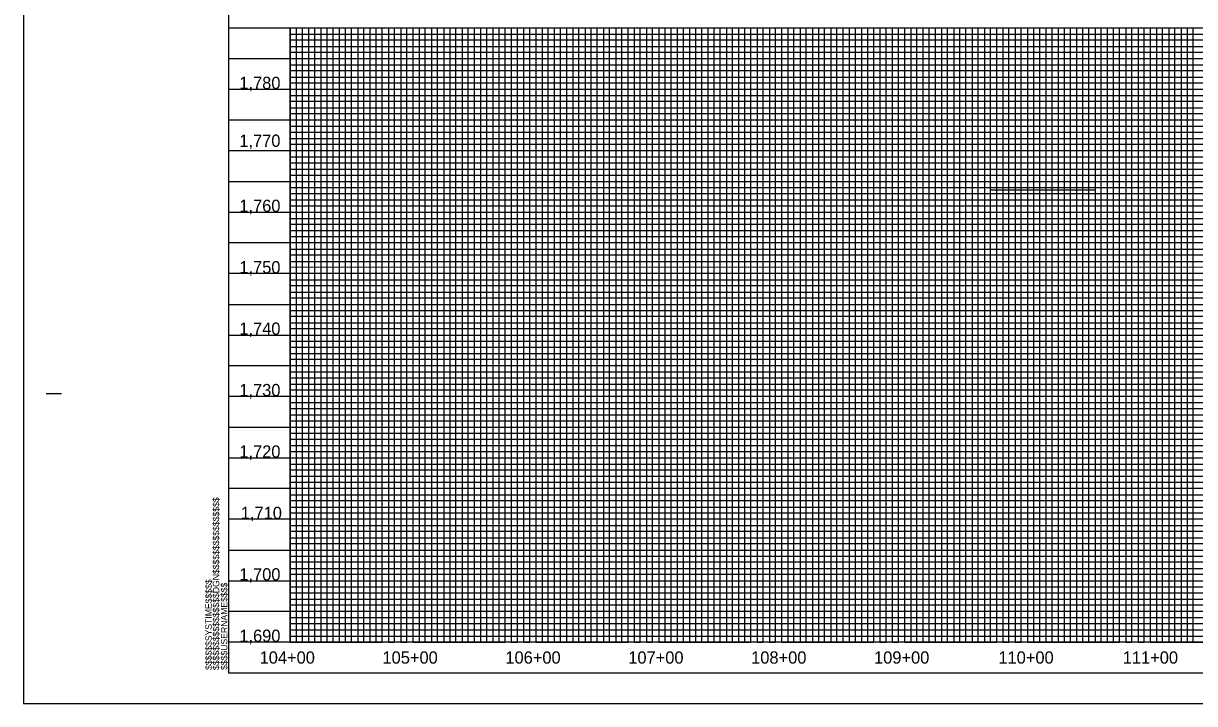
# Model space of a CAD drawing. Extents: x 505602 to 507286, y 483109 to 484209.
# Drawn here: x 505602 to 506555, y 483109 to 483662 of the extents above; entities that cross this region are included whole.
import ezdxf

# ---------------------------------------------------------------- set-up
doc = ezdxf.new("R2010")
doc.units = 0
for name, color, linetype in [('Exist Vertical Profile Vertical Axis Label', 7, 'Continuous'), ('Prop Grid Mask', 7, 'Continuous'), ('Sheet Layout Profile Border Port 2', 7, 'Continuous'), ('Sheet Plot Border Outside CELL', 7, 'Continuous'), ('Sheet Profile CELL', 7, 'Continuous'), ('Sheet Profile Grid Major CELL', 7, 'Continuous'), ('Sheet Profile Grid Middle CELL', 7, 'Continuous'), ('Sheet Profile Grid Minor CELL', 7, 'Continuous')]:
    doc.layers.add(name, color=color, linetype=linetype)

msp = doc.modelspace()

# ---------------------------------------------------------------- linework, layer by layer
at = {"layer": 'Prop Grid Mask'}
msp.add_lwpolyline([(506389.06, 483573.91), (506474.08, 483573.91), (506474.08, 483526.68), (506389.06, 483526.68)], close=True, dxfattribs=at)
at = {"layer": 'Sheet Layout Profile Border Port 2'}
msp.add_lwpolyline([(505819.08, 483658.71), (507219.08, 483658.71), (507219.08, 483158.71), (505819.08, 483158.71)], close=True, dxfattribs=at)
at = {"layer": 'Sheet Plot Border Outside CELL'}
msp.add_lwpolyline([(505602.08, 483108.71), (507286.08, 483108.71), (507286.08, 484208.71), (505602.08, 484208.71)], close=True, dxfattribs=at)
at = {"layer": 'Sheet Profile CELL'}
for p, q in [((505769.08, 483658.71), (507269.08, 483658.71)), ((505620.58, 483361.21), (505633.08, 483361.21)), ((507269.08, 483158.71), (505769.08, 483158.71)), ((505769.08, 483133.71), (507269.08, 483133.71)), ((505769.08, 483133.71), (505769.08, 483133.71)), ((505769.08, 483133.71), (505769.08, 483133.71)), ((505769.08, 483133.71), (505769.08, 483133.71)), ((505769.08, 483133.71), (505769.08, 483133.71)), ((505769.08, 483133.71), (505769.08, 483133.71)), ((505769.08, 483133.71), (505769.08, 483133.71)), ((505769.08, 483133.71), (505769.08, 483133.71))]:
    msp.add_line(p, q, dxfattribs=at)
msp.add_lwpolyline([(507269.08, 484183.71), (505769.08, 484183.71), (505769.08, 483133.71), (507269.08, 483133.71)], close=True, dxfattribs=at)
msp.add_lwpolyline([(505806.58, 483133.71), (505806.58, 483133.71)], dxfattribs=at)
at = {"layer": 'Sheet Profile Grid Major CELL'}
for p, q in [((506269.08, 483658.71), (506319.08, 483658.71)), ((506369.08, 483658.71), (506419.08, 483658.71)), ((506469.08, 483658.71), (506519.08, 483658.71))]:
    msp.add_line(p, q, dxfattribs=at)
for points in [[(505819.08, 483658.71), (505819.08, 483158.71), (505869.08, 483158.71), (505869.08, 483658.71), (505919.08, 483658.71), (505919.08, 483158.71), (505969.08, 483158.71), (505969.08, 483658.71), (506019.08, 483658.71), (506019.08, 483158.71), (506069.08, 483158.71), (506069.08, 483658.71), (506119.08, 483658.71), (506119.08, 483158.71), (506169.08, 483158.71), (506169.08, 483658.71), (506219.08, 483658.71), (506219.08, 483158.71), (506269.08, 483158.71), (506269.08, 483658.71), (506319.08, 483658.71), (506319.08, 483158.71), (506369.08, 483158.71), (506369.08, 483658.71), (506419.08, 483658.71), (506419.08, 483158.71), (506469.08, 483158.71), (506469.08, 483658.71), (506519.08, 483658.71), (506519.08, 483158.71), (506569.08, 483158.71)], [(507269.08, 483608.71), (505769.08, 483608.71)], [(507269.08, 483558.71), (505769.08, 483558.71), (505769.08, 483508.71), (507269.08, 483508.71)], [(507269.08, 483458.71), (505769.08, 483458.71), (505769.08, 483408.71), (507269.08, 483408.71)], [(507269.08, 483358.71), (505769.08, 483358.71), (505769.08, 483308.71), (507269.08, 483308.71)], [(507269.08, 483258.71), (505769.08, 483258.71), (505769.08, 483258.71), (505769.08, 483208.71), (507269.08, 483208.71)], [(507269.08, 483158.71), (505769.08, 483158.71)]]:
    msp.add_lwpolyline(points, dxfattribs=at)
at = {"layer": 'Sheet Profile Grid Middle CELL'}
for points in [[(505794.08, 483658.71), (505844.08, 483658.71), (505844.08, 483158.71), (505894.08, 483158.71), (505894.08, 483658.71), (505944.08, 483658.71), (505944.08, 483158.71), (505994.08, 483158.71), (505994.08, 483658.71), (506044.08, 483658.71), (506044.08, 483158.71), (506094.08, 483158.71), (506094.08, 483658.71), (506144.08, 483658.71), (506144.08, 483158.71), (506194.08, 483158.71), (506194.08, 483658.71), (506244.08, 483658.71), (506244.08, 483158.71), (506294.08, 483158.71), (506294.08, 483658.71), (506344.08, 483658.71), (506344.08, 483158.71), (506394.08, 483158.71), (506394.08, 483158.71), (506394.08, 483658.71), (506444.08, 483658.71), (506444.08, 483158.71), (506494.08, 483158.71), (506494.08, 483658.71), (506544.08, 483658.71), (506544.08, 483158.71), (506594.08, 483158.71)], [(505769.08, 483633.71), (507269.08, 483633.71)], [(507269.08, 483583.71), (505769.08, 483583.71), (505769.08, 483533.71), (507269.08, 483533.71)], [(507269.08, 483483.71), (505769.08, 483483.71), (505769.08, 483433.71), (507269.08, 483433.71)], [(507269.08, 483383.71), (505769.08, 483383.71), (505769.08, 483333.71), (507269.08, 483333.71)], [(507269.08, 483283.71), (505769.08, 483283.71), (505769.08, 483233.71), (507269.08, 483233.71)], [(507269.08, 483183.71), (505769.08, 483183.71)]]:
    msp.add_lwpolyline(points, dxfattribs=at)
at = {"layer": 'Sheet Profile Grid Minor CELL'}
for p, q in [((505819.08, 483653.71), (507219.08, 483653.71)), ((507219.08, 483648.71), (505819.08, 483648.71)), ((505819.08, 483643.71), (507219.08, 483643.71)), ((507219.08, 483638.71), (505819.08, 483638.71)), ((505819.08, 483628.71), (507219.08, 483628.71)), ((507219.08, 483623.71), (505819.08, 483623.71)), ((505819.08, 483618.71), (507219.08, 483618.71)), ((507219.08, 483613.71), (505819.08, 483613.71)), ((505819.08, 483603.71), (507219.08, 483603.71)), ((507219.08, 483598.71), (505819.08, 483598.71)), ((505819.08, 483593.71), (507219.08, 483593.71)), ((507219.08, 483588.71), (505819.08, 483588.71)), ((505819.08, 483578.71), (507219.08, 483578.71)), ((507219.08, 483573.71), (505819.08, 483573.71)), ((505819.08, 483568.71), (507219.08, 483568.71)), ((507219.08, 483563.71), (505819.08, 483563.71)), ((505819.08, 483553.71), (507219.08, 483553.71)), ((507219.08, 483548.71), (505819.08, 483548.71)), ((505819.08, 483543.71), (507219.08, 483543.71)), ((507219.08, 483538.71), (505819.08, 483538.71)), ((505819.08, 483528.71), (507219.08, 483528.71)), ((507219.08, 483523.71), (505819.08, 483523.71)), ((505819.08, 483518.71), (507219.08, 483518.71)), ((507219.08, 483513.71), (505819.08, 483513.71)), ((505819.08, 483503.71), (507219.08, 483503.71)), ((507219.08, 483498.71), (505819.08, 483498.71)), ((505819.08, 483493.71), (507219.08, 483493.71)), ((507219.08, 483488.71), (505819.08, 483488.71)), ((505819.08, 483478.71), (507219.08, 483478.71)), ((507219.08, 483473.71), (505819.08, 483473.71)), ((505819.08, 483468.71), (507219.08, 483468.71)), ((507219.08, 483463.71), (505819.08, 483463.86)), ((505819.08, 483453.71), (507219.08, 483453.71)), ((507219.08, 483448.71), (505819.08, 483448.71)), ((505819.08, 483443.71), (507219.08, 483443.71)), ((507219.08, 483438.71), (505819.08, 483438.71)), ((505819.08, 483428.71), (507219.08, 483428.71)), ((507219.08, 483423.71), (505819.08, 483423.71)), ((505819.08, 483418.71), (507219.08, 483418.71)), ((507219.08, 483413.71), (505819.08, 483413.71)), ((505819.08, 483403.71), (507219.08, 483403.71)), ((507219.08, 483398.71), (505819.08, 483398.71)), ((505819.08, 483393.71), (507219.08, 483393.71)), ((507219.08, 483388.71), (505819.08, 483388.71)), ((505819.08, 483378.71), (507219.08, 483378.71)), ((507219.08, 483373.71), (505819.08, 483373.71)), ((505819.08, 483368.71), (507219.08, 483368.71)), ((507219.08, 483363.71), (505819.08, 483363.71)), ((505819.08, 483353.71), (507219.08, 483353.71)), ((507219.08, 483348.71), (505819.08, 483348.71)), ((505819.08, 483343.71), (507219.08, 483343.71)), ((507219.08, 483338.71), (505819.08, 483338.71)), ((505819.08, 483328.71), (507219.08, 483328.71)), ((507219.08, 483323.71), (505819.08, 483323.71)), ((505819.08, 483318.71), (507219.08, 483318.71)), ((507219.08, 483313.71), (505819.08, 483313.71)), ((505819.08, 483303.71), (507219.08, 483303.71)), ((507219.08, 483298.71), (505819.08, 483298.71)), ((505819.08, 483293.71), (507219.08, 483293.71)), ((507219.08, 483288.71), (505819.08, 483288.71)), ((505819.08, 483278.71), (507219.08, 483278.71)), ((507219.08, 483273.71), (505819.08, 483273.71)), ((505819.08, 483268.71), (507219.08, 483268.71)), ((507219.08, 483263.71), (505819.08, 483263.71)), ((505819.08, 483253.71), (507219.08, 483253.71)), ((507219.08, 483248.71), (505819.08, 483248.71)), ((505819.08, 483243.71), (507219.08, 483243.71)), ((507219.08, 483238.71), (505819.08, 483238.71)), ((505819.08, 483228.71), (507219.08, 483228.71)), ((507219.08, 483223.71), (505819.08, 483223.71)), ((505819.08, 483218.71), (507219.08, 483218.71)), ((507219.08, 483213.71), (505819.08, 483213.71)), ((505819.08, 483203.71), (507219.08, 483203.71)), ((507219.08, 483198.71), (505819.08, 483198.71)), ((505819.08, 483193.71), (507219.08, 483193.71)), ((507219.08, 483188.71), (505819.08, 483188.71)), ((505819.08, 483178.71), (507219.08, 483178.71)), ((507219.08, 483173.71), (505819.08, 483173.71)), ((505819.08, 483168.71), (507219.08, 483168.71)), ((505819.08, 483163.71), (507219.08, 483163.71))]:
    msp.add_line(p, q, dxfattribs=at)
for points in [[(505819.08, 483658.71), (505824.08, 483658.71), (505824.08, 483158.71), (505829.08, 483158.71), (505829.08, 483658.71), (505834.08, 483658.71), (505834.08, 483158.71), (505839.08, 483158.71), (505839.08, 483658.71), (505849.08, 483658.71), (505849.08, 483158.71), (505854.08, 483158.71), (505854.08, 483658.71), (505859.08, 483658.71), (505859.08, 483158.71), (505864.08, 483158.71), (505874.08, 483158.71), (505879.08, 483158.71), (505879.08, 483658.71), (505884.08, 483658.71), (505884.08, 483158.71), (505889.08, 483158.71), (505889.08, 483658.71), (505899.08, 483658.71), (505899.08, 483158.71), (505904.08, 483158.71), (505904.08, 483658.71), (505909.08, 483658.71), (505909.08, 483158.71), (505914.08, 483158.71), (505914.08, 483658.71), (505924.08, 483658.71), (505924.08, 483158.71), (505929.08, 483158.71), (505929.08, 483658.71), (505934.08, 483658.71), (505934.08, 483158.71), (505939.08, 483158.71), (505939.08, 483658.71), (505949.08, 483658.71), (505949.08, 483158.71), (505954.08, 483158.71), (505954.08, 483658.71), (505959.08, 483658.71), (505959.08, 483158.71), (505964.08, 483158.71), (505964.08, 483658.71), (505974.08, 483658.71), (505974.08, 483158.71), (505979.08, 483158.71), (505979.08, 483658.71), (505984.08, 483658.71), (505984.08, 483158.71), (505989.08, 483158.71), (505989.08, 483658.71), (505999.08, 483658.71), (505999.08, 483158.71), (506004.08, 483158.71), (506004.08, 483658.71), (506009.08, 483658.71), (506009.08, 483158.71), (506014.08, 483158.71), (506014.08, 483658.71), (506024.08, 483658.71), (506024.08, 483158.71), (506029.08, 483158.71), (506029.08, 483658.71), (506034.08, 483658.71), (506034.08, 483158.71)], [(505864.08, 483158.71), (505864.08, 483658.71), (505874.08, 483658.71), (505874.08, 483158.71)], [(506034.08, 483158.71), (506039.08, 483158.71), (506039.08, 483658.71), (506049.08, 483658.71), (506049.08, 483158.71), (506054.08, 483158.71), (506054.08, 483658.71), (506059.08, 483658.71), (506059.08, 483158.71), (506064.08, 483158.71), (506064.08, 483658.71), (506074.08, 483658.71), (506074.08, 483158.71), (506079.08, 483158.71), (506079.08, 483658.71), (506084.08, 483658.71), (506084.08, 483158.71), (506089.08, 483158.71), (506089.08, 483658.71), (506099.08, 483658.71), (506099.08, 483158.71), (506104.08, 483158.71), (506104.08, 483658.71), (506109.08, 483658.71), (506109.08, 483158.71), (506114.08, 483158.71), (506114.08, 483658.71), (506124.08, 483658.71), (506124.08, 483158.71), (506129.08, 483158.71), (506129.08, 483658.71), (506134.08, 483658.71), (506134.08, 483158.71), (506139.08, 483158.71), (506139.08, 483658.71), (506149.08, 483658.71), (506149.08, 483158.71), (506154.08, 483158.71), (506154.08, 483658.71), (506159.08, 483658.71), (506159.08, 483158.71), (506164.08, 483158.71), (506164.08, 483658.71), (506174.08, 483658.71), (506174.08, 483158.71), (506179.08, 483158.71), (506179.08, 483658.71), (506184.08, 483658.71), (506184.08, 483158.71), (506189.08, 483158.71), (506189.08, 483658.71), (506199.08, 483658.71), (506199.08, 483158.71), (506204.08, 483158.71), (506204.08, 483658.71), (506209.08, 483658.71), (506209.08, 483158.71), (506214.08, 483158.71), (506214.08, 483658.71), (506224.08, 483658.71), (506224.08, 483158.71), (506229.08, 483158.71), (506229.08, 483658.71), (506234.08, 483658.71), (506234.08, 483158.71), (506239.08, 483158.71), (506239.08, 483658.71), (506249.08, 483658.71), (506249.08, 483158.71), (506254.08, 483158.71), (506254.08, 483658.71), (506259.08, 483658.71), (506259.08, 483158.71), (506264.08, 483158.71), (506264.08, 483658.71), (506274.08, 483658.71), (506274.08, 483158.71), (506279.08, 483158.71), (506279.08, 483658.71), (506284.08, 483658.71), (506284.08, 483158.71), (506289.08, 483158.71), (506289.08, 483658.71), (506299.08, 483658.71), (506299.08, 483158.71), (506304.08, 483158.71), (506304.08, 483658.71), (506309.08, 483658.71), (506309.08, 483158.71), (506314.08, 483158.71), (506314.08, 483658.71), (506324.08, 483658.71), (506324.08, 483158.71), (506329.08, 483158.71), (506329.08, 483658.71), (506334.08, 483658.71), (506334.08, 483158.71), (506339.08, 483158.71), (506339.08, 483658.71), (506349.08, 483658.71)], [(506349.08, 483658.71), (506349.08, 483158.71), (506354.08, 483158.71), (506354.08, 483658.71), (506359.08, 483658.71), (506359.08, 483158.71), (506364.08, 483158.71), (506364.08, 483658.71), (506374.08, 483658.71), (506374.08, 483158.71), (506379.08, 483158.71), (506379.08, 483658.71), (506384.08, 483658.71), (506384.08, 483158.71), (506389.08, 483158.71), (506389.08, 483658.71), (506399.08, 483658.71), (506399.08, 483158.71), (506404.08, 483158.71), (506404.08, 483658.71), (506409.08, 483658.71), (506409.08, 483158.71), (506414.08, 483158.71), (506414.08, 483658.71), (506424.08, 483658.71), (506424.08, 483158.71), (506429.08, 483158.71), (506429.08, 483658.71), (506434.08, 483658.71), (506434.08, 483158.71), (506439.08, 483158.71), (506439.08, 483658.71), (506449.08, 483658.71), (506449.08, 483158.71), (506454.08, 483158.71), (506454.08, 483658.71), (506459.08, 483658.71), (506459.08, 483158.71), (506464.08, 483158.71), (506464.08, 483658.71), (506474.08, 483658.71), (506474.08, 483158.71), (506474.08, 483158.71), (506479.08, 483158.71), (506479.08, 483658.71), (506484.08, 483658.71), (506484.08, 483158.71), (506489.08, 483158.71), (506489.08, 483658.71), (506499.08, 483658.71), (506499.08, 483158.71), (506504.08, 483158.71), (506504.08, 483658.71), (506509.08, 483658.71), (506509.08, 483158.71), (506514.08, 483158.71), (506514.08, 483658.71), (506524.08, 483658.71), (506524.08, 483158.71), (506529.08, 483158.71), (506529.08, 483658.71), (506534.08, 483658.71), (506534.08, 483158.71), (506539.08, 483158.71), (506539.08, 483658.71), (506549.08, 483658.71), (506549.08, 483158.71), (506554.08, 483158.71), (506554.08, 483658.71), (506559.08, 483658.71)]]:
    msp.add_lwpolyline(points, dxfattribs=at)

# ---------------------------------------------------------------- texts
at = {"layer": 'Exist Vertical Profile Vertical Axis Label'}
for s, p in [('1,780', (505777.78, 483608.96)), ('1,770', (505777.78, 483561.9)), ('1,760', (505777.78, 483508.91)), ('1,750', (505777.78, 483458.91)), ('1,740', (505777.78, 483408.91)), ('1,730', (505777.78, 483358.91)), ('1,720', (505777.78, 483308.91)), ('1,710', (505778.97, 483258.91)), ('1,700', (505777.78, 483208.91)), ('1,690', (505777.78, 483158.91)), ('104+00', (505794.26, 483141.21)), ('105+00', (505894.26, 483141.21)), ('106+00', (505994.26, 483141.21)), ('107+00', (506094.26, 483141.21)), ('108+00', (506194.26, 483141.21)), ('109+00', (506294.26, 483141.21)), ('110+00', (506395.45, 483141.21)), ('111+00', (506496.65, 483141.21))]:
    msp.add_text(s, height=10, dxfattribs=at).set_placement(p)
at = {"layer": 'Sheet Profile CELL'}
for s, p in [('$$$$$$$$$$$$$$$$DGN$$$$$$$$$$$$$$$$', (505761.44, 483136.09)), ('$$$$$$SYSTIME$$$$$', (505755.39, 483136.09)), ('$$$$USERNAME$$$$', (505768.02, 483136.1))]:
    msp.add_text(s, height=5.25, rotation=90, dxfattribs=at).set_placement(p)

doc.saveas('drawing.dxf')
